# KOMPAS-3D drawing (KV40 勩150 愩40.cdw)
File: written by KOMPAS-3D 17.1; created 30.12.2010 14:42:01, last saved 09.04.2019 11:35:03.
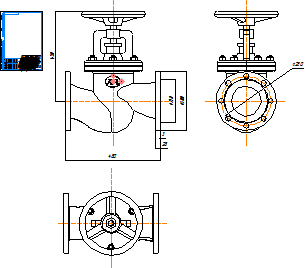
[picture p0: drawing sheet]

Title block, sheet 1: name: KV 40 Ду150; material: Внимание! Данный продукт является объектом авторского права ООО «Торговый Дом АДЛ». / Запрещается изменение, копирование, распространение / (в том числе путем копирования на другие сайты и ресурсы в Интернете) / или любое иное использование информации и объектов без предварительного / согласия правообладателя (ООО «Торговый Дом АДЛ»).; scale: 1:1; sheets: 1; organisation: ООО "Торговый дом АДЛ"; sheet format: A4; stored path: \\adlc.lan\data\АДЛ_ПКД\3D-модели\ADL production\Вентили ГРАНВЕНТ\KV40\KOMPAS 2D\KV 40 Ду150.cdw

Views: Проекционный вид 3, Спереди 1, Проекционный вид 2
Dimensions and other numbers on the sheet: 218; 300; 3; 28; 480; 450; 250; 1:1; 1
